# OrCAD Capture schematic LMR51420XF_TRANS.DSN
size D; title: LMR51420XF: SIMPLE SWITCHER® 4.5-V to 36-V, 2-A,; rev: 1.0; note: Datasheet: SLUSEF6B     EVM: SLUUCG9; note: Synchronous Step Down Converter; note: Synchronous Buck Converter in a SOT-23 Package
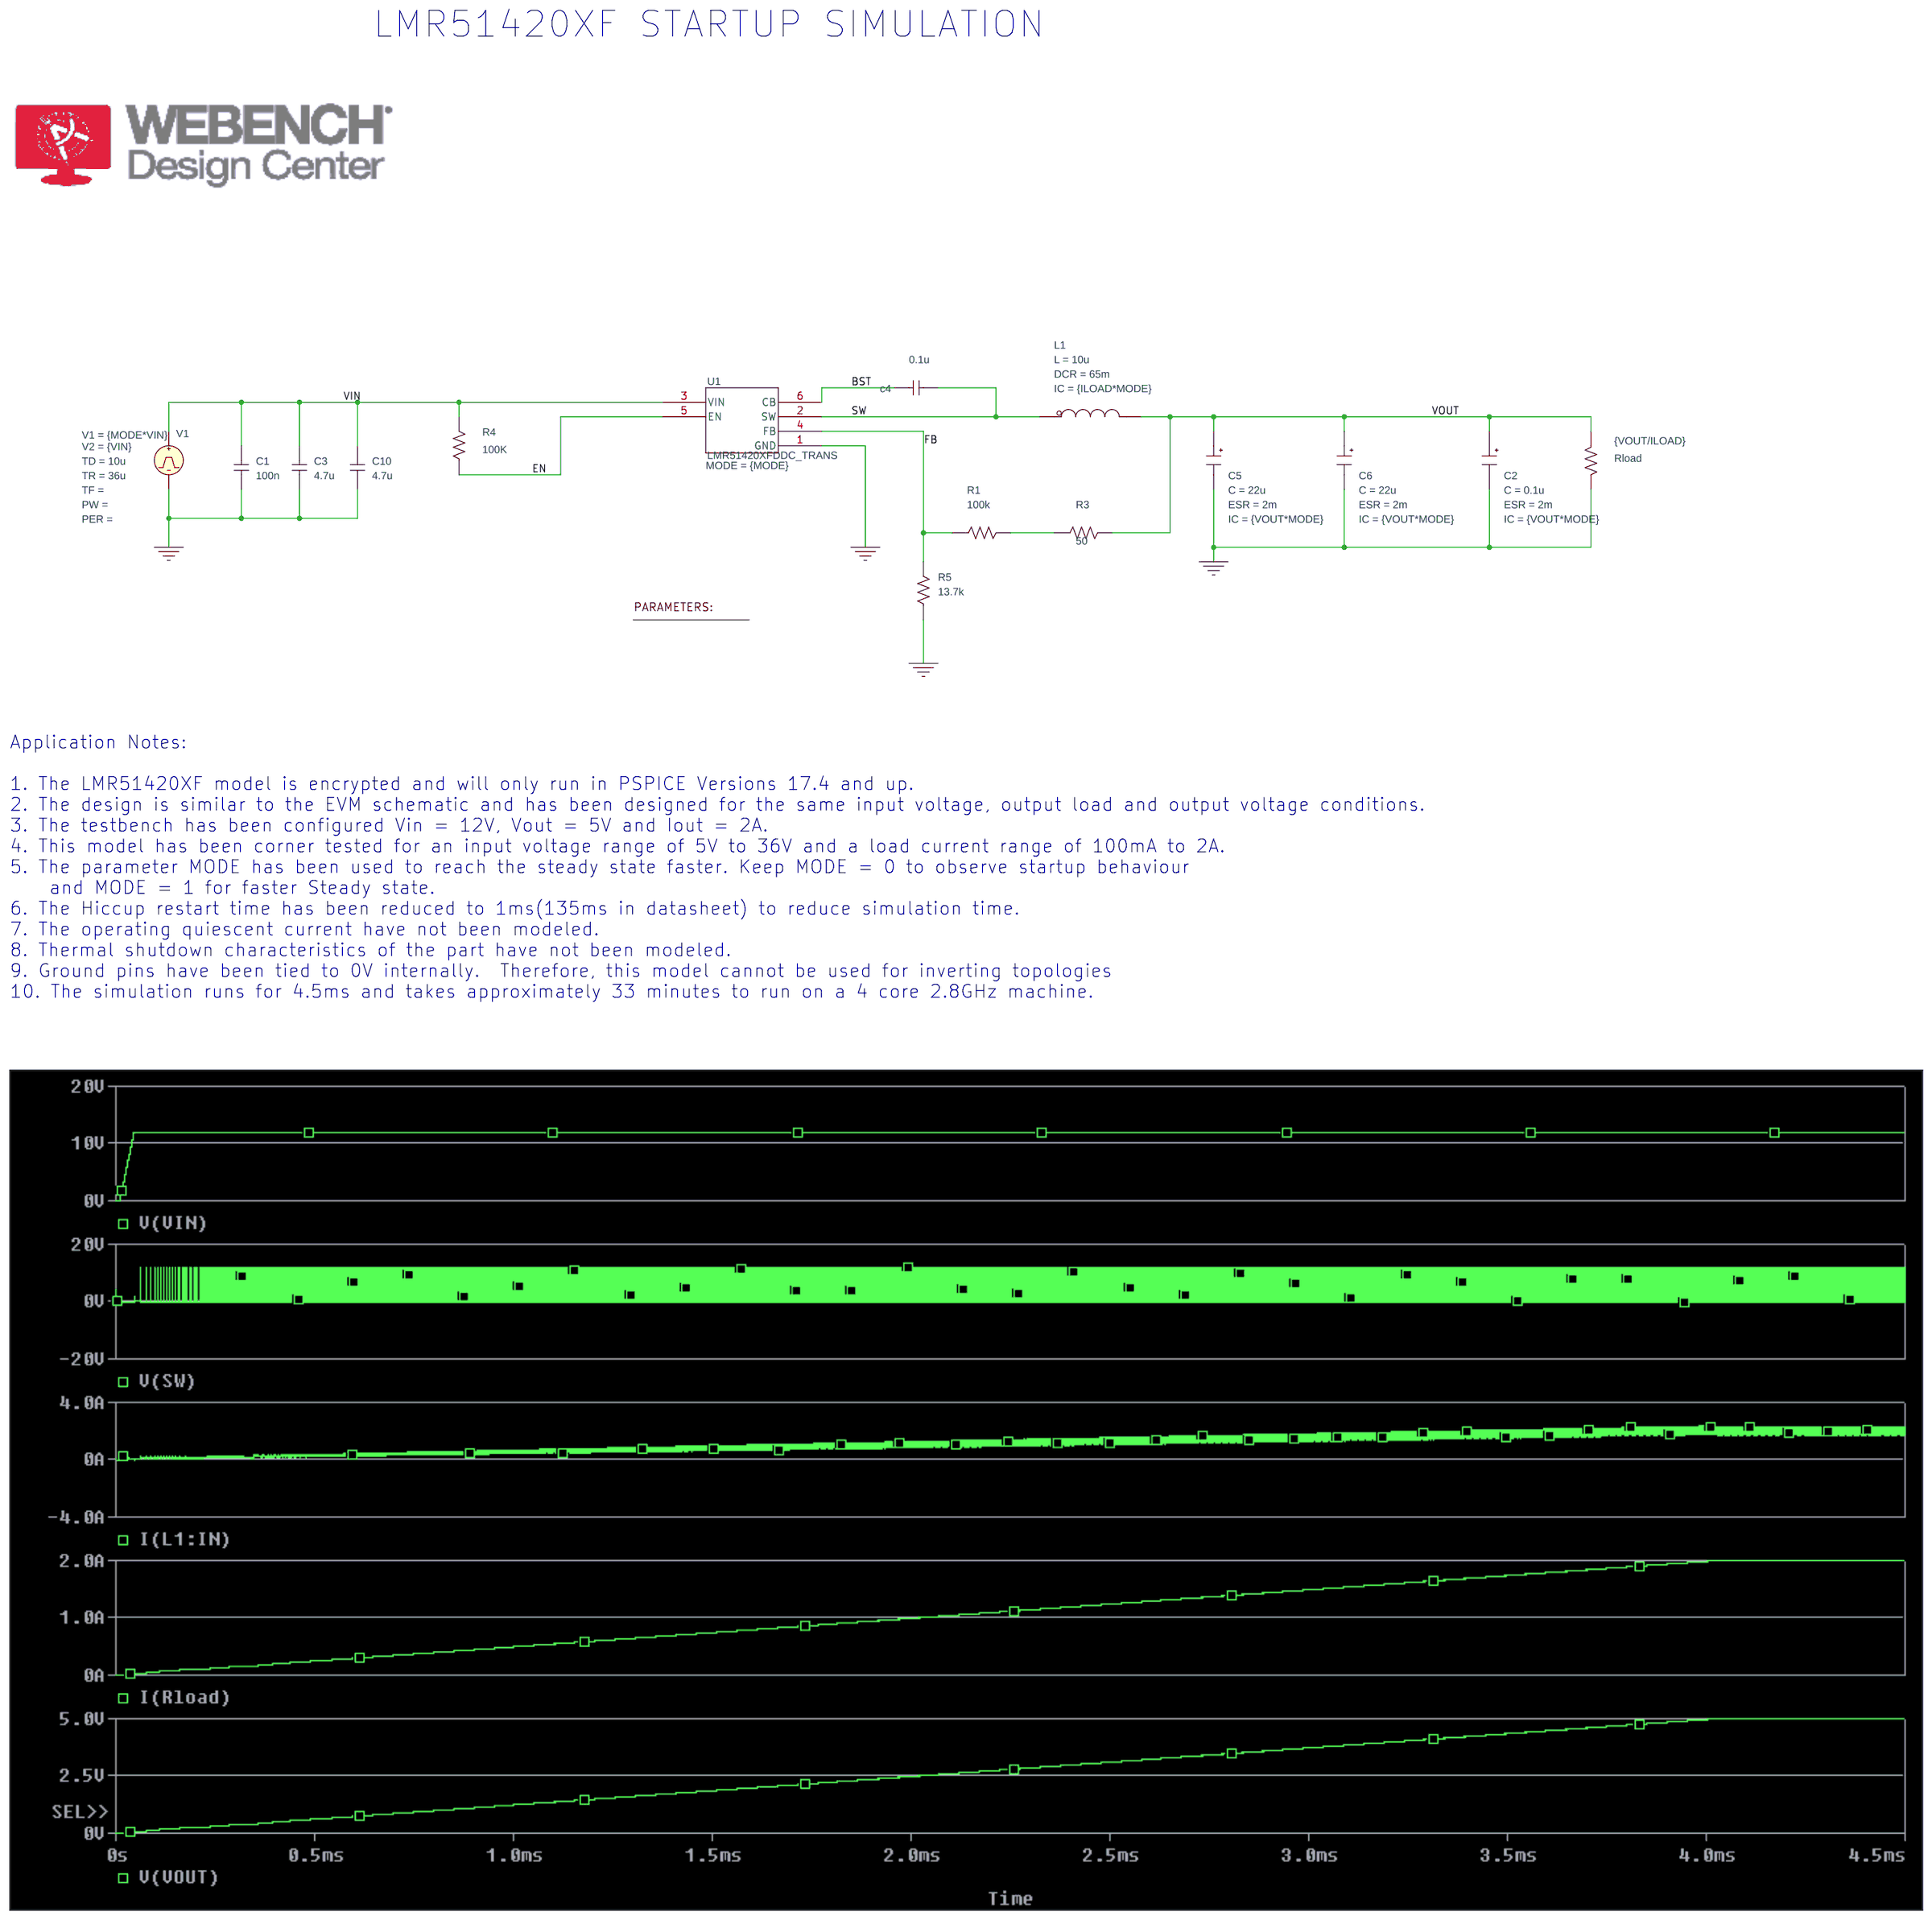
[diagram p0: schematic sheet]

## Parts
1  PARAM
C1  100n  [RAD/CK05]
C2  CESR
C3  4.7u  [RAD/CK05]
c4  0.1u  [RAD/CK05]
C5  CESR
C6  CESR
C10  4.7u  [RAD/CK05]
L1  LDCR
R1  100k  [RC05]
R3  50  [AX/RC05]
R4  100K  [AX/RC05]
R5  13.7k  [RC05]
Rload  {VOUT/ILOAD}  [AX/RC05]
U1  LMR51420XFDDC_TRANS  [DDC0006A-IPC_A]
V1  VPULSE

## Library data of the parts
1 = PARAM: ILOAD: 2; MODE: 0; VIN: 12; VOUT: 5
C1 C3 C10 = C
C2 = CESR_0: C: 0.1u; ESR: 2m; IC: {VOUT*MODE}; PSpiceTemplate: X^@REFDES %IN %OUT @MODEL PARAMS:  ?C|C=@C||C=100u|  ?ESR|ESR=@ESR||ESR=0.01| ?X|X=@X||X=2|  ?IC|IC=@IC||IC=2|; X: 1
c4 = C: IC: -3.3
C5 C6 = CESR_0: C: 22u; ESR: 2m; IC: {VOUT*MODE}; PSpiceTemplate: X^@REFDES %IN %OUT @MODEL PARAMS:  ?C|C=@C||C=100u|  ?ESR|ESR=@ESR||ESR=0.01| ?X|X=@X||X=2|  ?IC|IC=@IC||IC=2|; X: 1
L1 = LDCR_0: DCR: 65m; IC: {ILOAD*MODE}; L: 10u; PSpiceTemplate: X^@REFDES %IN %OUT @MODEL PARAMS:  ?L|L=@L||L=1u|  ?DCR|DCR=@DCR||DCR=0.01| ?IC|IC=@IC||IC=0|
R1 R3-R5 Rload = R
U1 = LMR51420XFDDC_TRANS: MODE: {MODE}
V1 = VPULSE: TD: 10u; TR: 36u; V1: {MODE*VIN}; V2: {VIN}

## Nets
VIN: C1.2 C3.2 C10.2 R4.2 U1.3(VIN) V1.1(+)
0: C1.1 C2.3(OUT) C3.1 C5.3(OUT) C6.3(OUT) C10.1 R5.1 Rload.2 U1.1(GND) V1.2(-)
BST: c4.1 U1.6(CB)
EN: R4.1 U1.5(EN)
FB: R1.1 R5.2 U1.4(FB)
SW: c4.2 L1.1(IN) U1.2(SW)
VOUT: C2.1(IN) C5.1(IN) C6.1(IN) L1.3(OUT) R3.2 Rload.1
N16770388: R1.2 R3.1

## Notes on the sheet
- LMR51420XF STARTUP SIMULATION
- Application Notes:
  1. The LMR51420XF model is encrypted and will only run in PSPICE Versions 17.4 and up.
  2. The design is similar to the EVM schematic and has been designed for the same input voltage, output load and output voltage conditions.
  3. The testbench has been configured Vin = 12V, Vout = 5V and Iout = 2A.
  4. This model has been corner tested for an input voltage range of 5V to 36V and a load current range of 100mA to 2A.
  5. The parameter MODE has been used to reach the steady state faster. Keep MODE = 0 to observe startup behaviour
      and MODE = 1 for faster Steady state.
  6. The Hiccup restart time has been reduced to 1ms(135ms in datasheet) to reduce simulation time.
  7. The operating quiescent current have not been modeled.
  8. Thermal shutdown characteristics of the part have not been modeled.
  9. Ground pins have been tied to 0V internally.  Therefore, this model cannot be used for inverting topologies
  10. The simulation runs for 4.5ms and takes approximately 33 minutes to run on a 4 core 2.8GHz machine.
